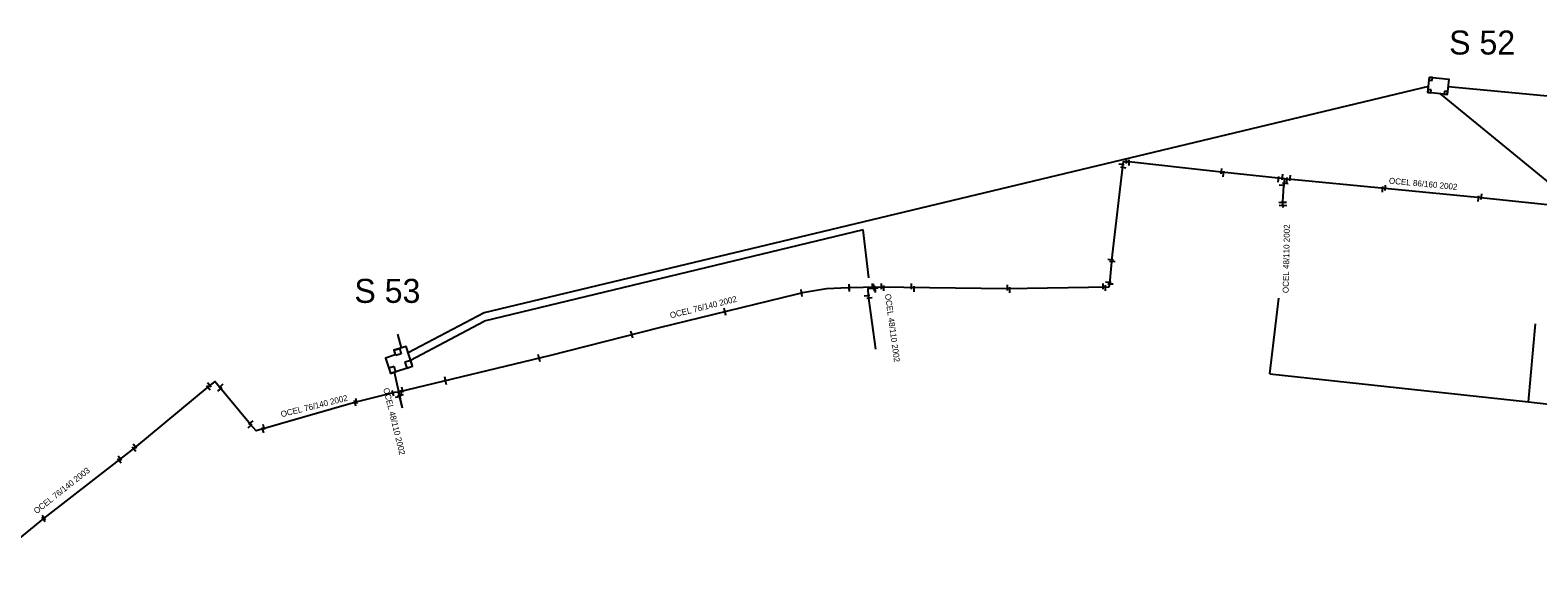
# Model space of a CAD drawing. Extents: x -642943 to -623314, y -1138561 to -1113539.
# Drawn here: x -642840.5 to -642652, y -1114156.8 to -1114087.9 of the extents above; entities that cross this region are included whole.
import ezdxf

# ---------------------------------------------------------------- set-up
doc = ezdxf.new("R2010")
doc.units = 0
for name, color, linetype in [('horkovod dimenze', 7, 'Continuous'), ('horkovod předisol', 7, 'Continuous'), ('horkovod sváry', 7, 'Continuous'), ('horkovod trasa', 7, 'Continuous'), ('horkovod zrušený', 7, 'Continuous'), ('horkovod číslo šachty', 7, 'Continuous')]:
    doc.layers.add(name, color=color, linetype=linetype)

# ---------------------------------------------------------------- blocks, each defined once
blk = doc.blocks.new('POINT_DISPLAY')
blk.add_line((0, 0), (0, 0))
blk = doc.blocks.new('SPH')
at = {"layer": 'horkovod sváry'}
blk.add_line((0, -0.035), (0, 0.035), dxfattribs=at)

msp = doc.modelspace()

# ---------------------------------------------------------------- linework, layer by layer
at = {"layer": 'horkovod předisol'}
for q in [(-642794.96, -1114133.17), (-642793.99, -1114135.1)]:
    msp.add_line((-642794.48, -1114133.13), q, dxfattribs=at)
for points in [[(-642683.7, -1114106.45), (-642692.33, -1114105.57), (-642703.17, -1114104.35), (-642703.88, -1114104.34), (-642703.96, -1114104.94), (-642705.25, -1114115.93), (-642705.59, -1114119.6), (-642705.68, -1114120), (-642718.4, -1114120.21), (-642734.48, -1114120.02)], [(-642683.7, -1114106.45), (-642683.84, -1114107.34), (-642683.94, -1114109.33), (-642683.93, -1114110.05)], [(-642646.93, -1114110.09), (-642647.68, -1114110.06), (-642659.59, -1114108.78), (-642670.77, -1114107.73), (-642683.7, -1114106.45)], [(-642734.48, -1114120.02), (-642738.26, -1114120.08), (-642740.95, -1114120.23), (-642743.94, -1114120.73), (-642744.78, -1114120.93), (-642761.86, -1114125.1), (-642775.44, -1114128.53), (-642794.48, -1114133.13)], [(-642734.48, -1114120.02), (-642734.57, -1114120.13), (-642735.79, -1114120.22), (-642735.75, -1114121.09), (-642734.81, -1114127.75)], [(-642794.96, -1114133.17), (-642799.79, -1114134.4), (-642812.23, -1114137.95), (-642812.93, -1114137.17), (-642817.38, -1114131.8), (-642818.13, -1114132.4), (-642827.45, -1114140.07), (-642829.31, -1114141.55), (-642838.8, -1114148.94), (-642848.09, -1114156.5), (-642848.49, -1114156.84)]]:
    msp.add_lwpolyline(points, dxfattribs=at)
at = {"layer": 'horkovod trasa'}
for q in [(-642794.96, -1114133.17), (-642793.99, -1114135.1)]:
    msp.add_line((-642794.48, -1114133.13), q, dxfattribs=at)
for points in [[(-642683.7, -1114106.45), (-642692.33, -1114105.57), (-642703.17, -1114104.35), (-642703.88, -1114104.34), (-642703.96, -1114104.94), (-642705.25, -1114115.93), (-642705.59, -1114119.6), (-642705.68, -1114120), (-642718.4, -1114120.21), (-642734.48, -1114120.02)], [(-642683.7, -1114106.45), (-642683.84, -1114107.34), (-642683.94, -1114109.33), (-642683.93, -1114110.05)], [(-642646.93, -1114110.09), (-642647.68, -1114110.06), (-642659.59, -1114108.78), (-642670.77, -1114107.73), (-642683.7, -1114106.45)], [(-642734.48, -1114120.02), (-642738.26, -1114120.08), (-642740.95, -1114120.23), (-642743.94, -1114120.73), (-642744.78, -1114120.93), (-642761.86, -1114125.1), (-642775.44, -1114128.53), (-642794.48, -1114133.13)], [(-642734.48, -1114120.02), (-642734.57, -1114120.13), (-642735.79, -1114120.22), (-642735.75, -1114121.09), (-642734.81, -1114127.75)], [(-642794.96, -1114133.17), (-642799.79, -1114134.4), (-642812.23, -1114137.95), (-642812.93, -1114137.17), (-642817.38, -1114131.8), (-642818.13, -1114132.4), (-642827.45, -1114140.07), (-642829.31, -1114141.55), (-642838.8, -1114148.94), (-642848.09, -1114156.5), (-642848.49, -1114156.84)]]:
    msp.add_lwpolyline(points, dxfattribs=at)
at = {"layer": 'horkovod zrušený'}
for p, q in [((-642665.7, -1114094.94), (-642783.75, -1114123.21)), ((-642665.58, -1114093.76), (-642665.61, -1114094.14)), ((-642665.61, -1114094.14), (-642665.24, -1114094.18)), ((-642665.2, -1114093.8), (-642665.58, -1114093.76)), ((-642665.24, -1114094.18), (-642665.2, -1114093.8)), ((-642512.97, -1114109.11), (-642663.27, -1114094.95)), ((-642665.74, -1114095.31), (-642665.78, -1114095.68)), ((-642665.78, -1114095.68), (-642665.4, -1114095.72)), ((-642665.36, -1114095.35), (-642665.74, -1114095.31)), ((-642665.4, -1114095.72), (-642665.36, -1114095.35)), ((-642664.26, -1114095.84), (-642645.82, -1114110.94)), ((-642663.7, -1114095.52), (-642663.74, -1114095.89)), ((-642663.74, -1114095.89), (-642663.37, -1114095.93)), ((-642663.33, -1114095.56), (-642663.7, -1114095.52)), ((-642663.37, -1114095.93), (-642663.33, -1114095.56)), ((-642736.35, -1114112.83), (-642783.74, -1114124.27)), ((-642735.67, -1114118.85), (-642736.35, -1114112.83)), ((-642783.75, -1114123.21), (-642793.23, -1114128.22)), ((-642685.54, -1114130.85), (-642684.42, -1114121.37)), ((-642792.94, -1114129.13), (-642783.74, -1114124.27)), ((-642653.21, -1114134.33), (-642652.34, -1114124.57)), ((-642794.05, -1114127.59), (-642794.51, -1114125.9)), ((-642794.99, -1114127.9), (-642794.33, -1114127.69)), ((-642794.78, -1114128.56), (-642794.99, -1114127.9)), ((-642794.78, -1114128.56), (-642794.96, -1114127.99)), ((-642794.11, -1114128.35), (-642794.78, -1114128.56)), ((-642794.33, -1114127.69), (-642794.11, -1114128.35)), ((-642794.99, -1114129.91), (-642795.67, -1114130.12)), ((-642795.67, -1114130.12), (-642795.46, -1114130.79)), ((-642795.46, -1114130.79), (-642794.79, -1114130.58)), ((-642794.79, -1114130.58), (-642794.99, -1114129.91)), ((-642793.94, -1114135.11), (-642794.95, -1114130.61)), ((-642792.92, -1114129.17), (-642793.64, -1114129.4)), ((-642793.64, -1114129.4), (-642793.41, -1114130.11)), ((-642793.41, -1114130.11), (-642792.7, -1114129.89)), ((-642792.7, -1114129.89), (-642792.92, -1114129.17)), ((-642685.54, -1114130.85), (-642653.21, -1114134.33)), ((-642653.21, -1114134.33), (-642603.66, -1114140.09))]:
    msp.add_line(p, q, dxfattribs=at)
for points in [[(-642665.58, -1114093.76), (-642663.17, -1114094), (-642663.37, -1114095.93), (-642665.78, -1114095.68), (-642665.58, -1114093.75)], [(-642794.85, -1114128.47), (-642796.07, -1114128.86), (-642795.46, -1114130.77), (-642792.7, -1114129.89), (-642793.48, -1114127.41), (-642795.03, -1114127.9), (-642794.85, -1114128.47)]]:
    msp.add_lwpolyline(points, dxfattribs=at)

# ---------------------------------------------------------------- block references
at = {"layer": 'horkovod sváry'}
for p, xscale, yscale, rotation in [((-642703.49, -1114104.22), 10.000009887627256, 10.000009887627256, 178.9191110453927), ((-642703.15, -1114104.46), 9.999995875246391, 9.999995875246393, 179.01223960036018), ((-642704.08, -1114104.69), 10.000013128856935, 10.000013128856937, 82.875049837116), ((-642703.83, -1114105.08), 10.000014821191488, 10.000014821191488, 80.98056045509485), ((-642691.57, -1114105.51), 10.000005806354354, 10.000005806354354, -5.545649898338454), ((-642691.32, -1114105.85), 10.000018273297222, 10.000018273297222, -5.852651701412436), ((-642684.44, -1114106.53), 9.99999567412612, 9.99999567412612, -7.386121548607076), ((-642683.97, -1114106.25), 10.000011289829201, 10.000011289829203, -6.483031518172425), ((-642683.03, -1114106.35), 9.999987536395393, 9.999987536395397, 174.28945995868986), ((-642684.03, -1114107.28), 10.000010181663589, 10.00001018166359, 84.23745235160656), ((-642683.6, -1114107.06), 10.000006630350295, 10.000006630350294, 84.56585271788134), ((-642683.43, -1114106.64), 9.99997936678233, 9.999979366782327, 175.13536678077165), ((-642671.43, -1114107.78), 9.999994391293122, 9.99999439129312, -5.643506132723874), ((-642671.1, -1114107.59), 10.000002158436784, 10.000002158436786, -5.374386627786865), ((-642684.07, -1114109.45), 9.999998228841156, 9.999998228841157, 89.21877144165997), ((-642684.04, -1114109.81), 10.000000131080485, 10.000000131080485, 87.62155334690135), ((-642683.8, -1114109.42), 9.999994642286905, 9.999994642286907, 87.85919332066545), ((-642683.77, -1114109.81), 10.000020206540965, 10.000020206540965, 88.0183170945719), ((-642659.45, -1114108.94), 9.999983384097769, 9.999983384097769, -6.434180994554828), ((-642659.07, -1114108.69), 9.999994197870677, 9.999994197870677, -6.0342690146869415), ((-642705.43, -1114116.55), 9.999985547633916, 9.999985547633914, -95.95459746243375), ((-642705.21, -1114116.78), 9.999985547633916, 9.999985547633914, -95.95459746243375), ((-642705.72, -1114119.37), 10.000016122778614, 10.000016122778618, -92.93319337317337), ((-642744.07, -1114120.66), 10.000033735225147, 10.000033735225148, 9.375650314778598), ((-642744.03, -1114120.84), 10.000021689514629, 10.000021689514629, 9.138046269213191), ((-642738.12, -1114119.98), 10.00000611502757, 10.000006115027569, 2.1210470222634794), ((-642738.07, -1114120.19), 10.000005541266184, 10.000005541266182, 2.3533443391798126), ((-642735.89, -1114121.03), 9.999995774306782, 9.99999577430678, -83.57710371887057), ((-642735.57, -1114121.33), 10.000002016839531, 10.000002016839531, -84.26989404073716), ((-642735.19, -1114119.88), 10.000010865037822, 10.00001086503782, 2.0559024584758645), ((-642735.06, -1114119.96), 9.999991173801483, 9.999991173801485, 1.0608771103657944), ((-642734.95, -1114120.16), 10.000003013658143, 10.000003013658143, 1.8999972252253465), ((-642734.84, -1114120.32), 10.000003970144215, 10.000003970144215, 4.6177825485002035), ((-642705.45, -1114119.63), 9.999988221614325, 9.999988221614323, 88.38081155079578), ((-642753.64, -1114122.97), 9.999981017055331, 9.999981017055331, 13.519528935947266), ((-642753.61, -1114123.19), 9.999993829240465, 9.999993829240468, 12.913005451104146), ((-642765.33, -1114125.84), 10.000016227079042, 10.000016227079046, 14.005959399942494), ((-642765.23, -1114126.04), 9.999980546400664, 9.999980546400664, 13.844378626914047), ((-642776.91, -1114128.75), 9.999993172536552, 9.999993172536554, 14.567647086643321), ((-642776.81, -1114129.02), 10.00001839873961, 10.000018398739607, 14.486302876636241), ((-642818.21, -1114132.63), 10.000021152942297, 10.000021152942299, 39.28946317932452), ((-642818.08, -1114132.22), 9.9999906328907, 9.999990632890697, 39.71873411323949), ((-642816.8, -1114132.79), 9.999986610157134, 9.999986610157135, 130.12613855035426), ((-642816.66, -1114132.38), 9.999985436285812, 9.999985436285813, 132.31627784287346), ((-642793.95, -1114132.84), 9.999982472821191, 9.999982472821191, 13.861138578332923), ((-642788.59, -1114131.55), 9.999993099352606, 9.999993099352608, 13.724858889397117), ((-642788.54, -1114131.87), 10.000017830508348, 10.00001783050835, 13.820695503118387), ((-642799.85, -1114134.53), 10.00001442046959, 10.000014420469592, 15.289961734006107), ((-642799.7, -1114134.27), 9.999982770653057, 9.999982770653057, 15.612772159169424), ((-642795.17, -1114133.26), 10.000014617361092, 10.00001461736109, -164.91268499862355), ((-642794.51, -1114133.73), 9.999989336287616, 9.999989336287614, 100.78432282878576), ((-642794.21, -1114133.54), 10.00001096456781, 10.00001096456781, 102.81035640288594), ((-642794.09, -1114133.21), 10.000019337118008, 10.000019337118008, 13.561464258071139), ((-642812.98, -1114137.37), 9.999980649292, 9.999980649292, -48.87122509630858), ((-642812.87, -1114136.96), 9.999994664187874, 9.999994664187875, -49.727888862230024), ((-642811.37, -1114137.88), 10.000020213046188, 10.000020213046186, 15.974274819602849), ((-642811.27, -1114137.49), 9.999988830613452, 9.999988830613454, 15.980431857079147), ((-642827.5, -1114140.26), 10.000004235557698, 10.000004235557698, 40.21683684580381), ((-642827.39, -1114139.9), 10.000008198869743, 10.000008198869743, 39.10361709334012), ((-642829.33, -1114141.73), 9.999990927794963, 9.999990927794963, 38.81239640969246), ((-642829.28, -1114141.4), 9.999996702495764, 9.999996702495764, 38.48134430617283), ((-642838.81, -1114149.06), 10.000002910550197, 10.000002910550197, 37.204525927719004), ((-642838.76, -1114148.8), 9.999996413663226, 9.999996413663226, 38.04706993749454)]:
    msp.add_blockref('SPH', p, dxfattribs=dict(at, xscale=xscale, yscale=yscale, rotation=rotation))
at = {"layer": 'horkovod sváry', "xscale": 10, "yscale": 10}
for p in [(-642734.09, -1114119.89), (-642733.79, -1114120.13), (-642730.33, -1114119.89), (-642730.01, -1114120.23), (-642718.33, -1114120.08), (-642718.04, -1114120.35), (-642706.39, -1114119.91), (-642706.09, -1114120.11)]:
    msp.add_blockref('SPH', p, dxfattribs=at)
at = {"layer": 'horkovod zrušený'}
for p in [(-642794.55, -1114128.12), (-642795.23, -1114130.35), (-642793.16, -1114129.65)]:
    msp.add_blockref('POINT_DISPLAY', p, dxfattribs=at)

# ---------------------------------------------------------------- texts
at = {"layer": 'horkovod dimenze'}
for s, rotation, p in [('OCEL 86/160 2002', 354.6728, (-642670.68, -1114107.06)), ('OCEL 48/110 2002', 88.944, (-642683.19, -1114120.75)), ('OCEL 76/140 2002', 14.1061, (-642760.42, -1114123.91)), ('OCEL 48/110 2002', 277.6944, (-642733.65, -1114120.9)), ('OCEL 48/110 2002', 283.8257, (-642796.36, -1114132.7)), ('OCEL 76/140 2002', 14.1061, (-642809.06, -1114136.27)), ('OCEL 76/140 2003', 38.419, (-642839.67, -1114148.39))]:
    msp.add_text(s, height=0.75, rotation=rotation, dxfattribs=at).set_placement(p)
at = {"layer": 'horkovod číslo šachty'}
for s, p in [('S 52', (-642663.13, -1114090.93)), ('S 53', (-642799.96, -1114121.97))]:
    msp.add_text(s, height=3, dxfattribs=at).set_placement(p)

doc.saveas('drawing.dxf')
